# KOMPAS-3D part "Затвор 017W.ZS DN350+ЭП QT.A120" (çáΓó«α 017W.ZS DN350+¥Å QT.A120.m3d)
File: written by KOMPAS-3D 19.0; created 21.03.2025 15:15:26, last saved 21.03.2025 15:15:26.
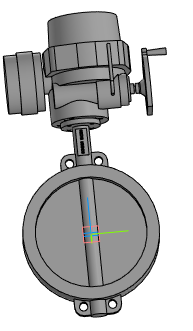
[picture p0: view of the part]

Document properties: Полное имя файла: Затвор 017W.ZS DN350+ЭП QT.A120.a3d

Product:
- Part/product: Затвор 017W.ZS DN350+ЭП QT.A120
    Масса: 192.916

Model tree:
1. Операция без истории:1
